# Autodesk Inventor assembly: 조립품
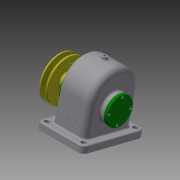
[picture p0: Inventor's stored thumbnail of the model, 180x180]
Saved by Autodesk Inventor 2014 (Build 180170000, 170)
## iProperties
Created: 2016-10
Part Number: 조립품
Document SubType Name: Assembly
Designer: USER
Author: USER
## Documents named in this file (15)
- C:\Users\USER\Desktop\461008V1011\조립품.iam
- C:\Users\USER\Desktop\461008V1011\V-벨트풀리.ipt
- C:\Users\USER\Desktop\461008V1011\뒤커버.ipt
- C:\Users\USER\Desktop\461008V1011\멈춤나사 - M4x10.ipt
- C:\Users\USER\Desktop\461008V1011\베어링 6203.ipt
- C:\Users\USER\Desktop\461008V1011\본체.ipt
- C:\Users\USER\Desktop\461008V1011\볼트 M3 x 8.ipt
- C:\Users\USER\Desktop\461008V1011\볼트 M3 x 10.ipt
- C:\Users\USER\Desktop\461008V1011\부시.ipt
- C:\Users\USER\Desktop\461008V1011\스퍼기어.ipt
- C:\Users\USER\Desktop\461008V1011\앞커버.ipt
- C:\Users\USER\Desktop\461008V1011\오일씰 28 40 8.ipt
- C:\Users\USER\Desktop\461008V1011\축.ipt
- C:\Users\USER\Desktop\461008V1011\키 - 5 x 5 x 18.ipt
- C:\Users\USER\Desktop\461008V1011\키 - 6 x 6 x 22.ipt
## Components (9 placed, 3 different names)
1. V-벨트풀리:1
2. ISO 4762 M3 x 8:1
3. ISO 4762 M3 x 8:2
4. ISO 4762 M3 x 8:3
5. ISO 4762 M3 x 8:4
6. ISO 4762 M3 x 10:1
7. ISO 4762 M3 x 10:2
8. ISO 4762 M3 x 10:3
9. ISO 4762 M3 x 10:4
